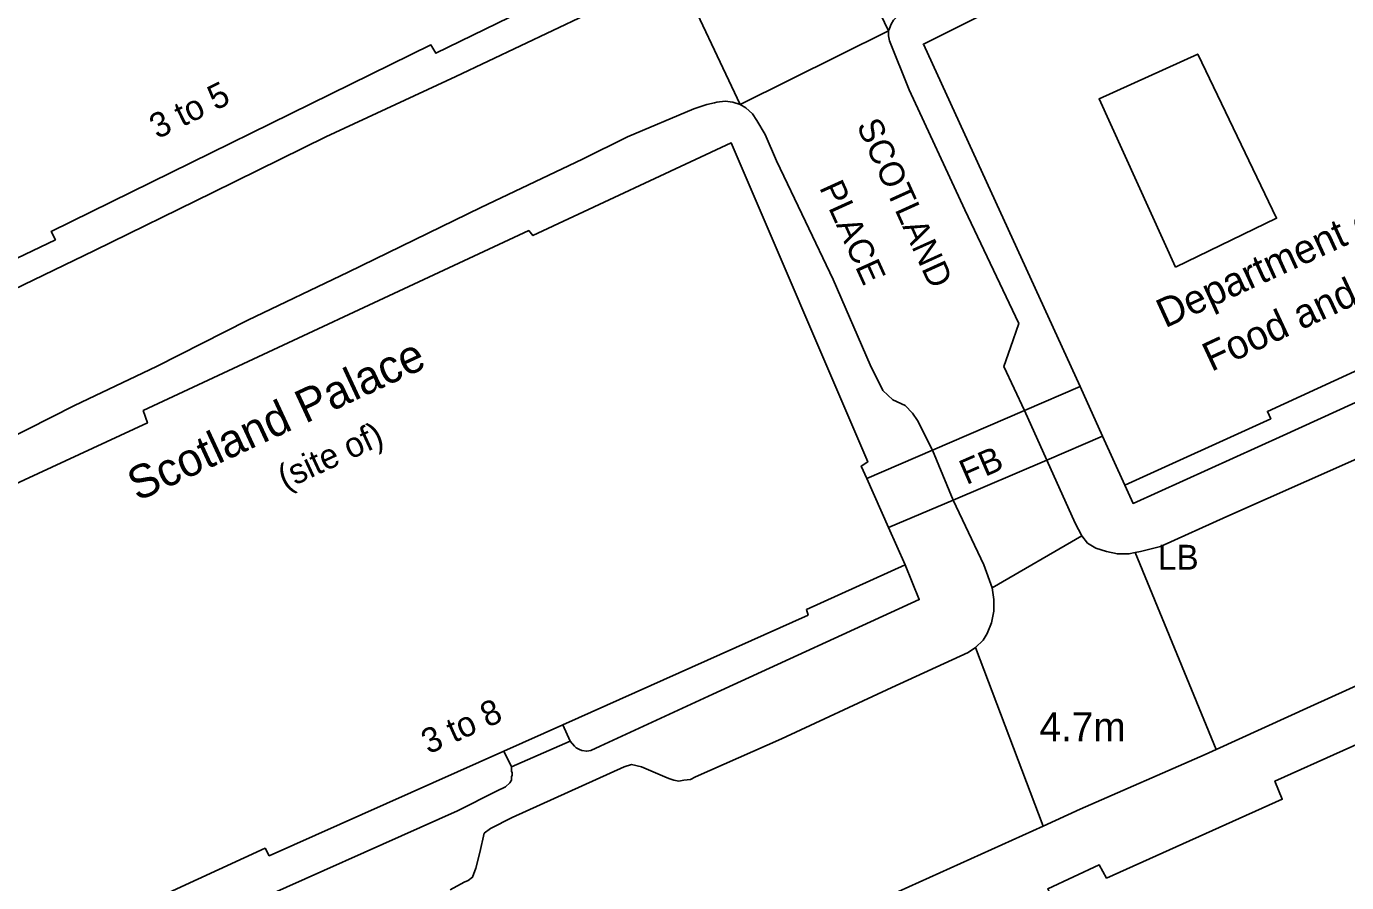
# Model space of a CAD drawing. Extents: x 529240 to 530363, y 179600 to 180767.
# Drawn here: x 530125.5 to 530205.1, y 180212.1 to 180263.8 of the extents above; entities that cross this region are included whole.
import ezdxf

# ---------------------------------------------------------------- set-up
doc = ezdxf.new("R2010")
doc.units = 0
for name, color, linetype in [('Building', 7, 'Continuous'), ('General surface', 7, 'Continuous'), ('Road Or Track', 7, 'Continuous'), ('Roadside', 7, 'Continuous'), ('Structure', 7, 'Continuous'), ('Unclassified', 7, 'Continuous')]:
    doc.layers.add(name, color=color, linetype=linetype)

msp = doc.modelspace()

# ---------------------------------------------------------------- linework, layer by layer
at = {"layer": 'Building'}
for points in [[(530120.25, 180247.55), (530127.25, 180250.9), (530127, 180251.4), (530149.9, 180262.65), (530150.2, 180262.15), (530156.85, 180265.4), (530156.7, 180265.6), (530153.1, 180272.85), (530151.05, 180271.9), (530149.15, 180275.8), (530145.1, 180284.25), (530141.55, 180291.4), (530143.35, 180292.35), (530140.7, 180297.2), (530139.75, 180299.05), (530137.25, 180297.85), (530138.3, 180295.75), (530133.7, 180293.55), (530133.15, 180294.6), (530128.85, 180292.5), (530129.4, 180291.2), (530123.5, 180288.35)], [(530206.8, 180276.35), (530200.35, 180273.1), (530179.6, 180262.7), (530189.05, 180242.05), (530190.4, 180239.05), (530191.75, 180236.1), (530200.55, 180240.1), (530200.35, 180240.55), (530210.15, 180245.05)], [(530206.8, 180276.35), (530200.35, 180273.1), (530179.6, 180262.7), (530189.05, 180242.05)], [(530116.9, 180254.6), (530120.25, 180247.55), (530127.25, 180250.9), (530127, 180251.4), (530149.9, 180262.65), (530150.2, 180262.15), (530156.85, 180265.4), (530156.7, 180265.6)], [(530194.8, 180249.25), (530190.2, 180259.4), (530196.15, 180262.1), (530200.9, 180252.2), (530194.8, 180249.25)], [(530133.05, 180211.05), (530139.9, 180214.2), (530140.15, 180213.75), (530154.3, 180220.05), (530157.85, 180221.65), (530172.65, 180228.25), (530172.55, 180228.6), (530178.5, 180231.3), (530177.5, 180233.55), (530176.2, 180236.5), (530175.85, 180237.25), (530176.25, 180237.5), (530168, 180256.75), (530156.05, 180251.15), (530155.8, 180251.45), (530132.55, 180240.6), (530132.8, 180239.85), (530104.2, 180226.6), (530106.65, 180221.35), (530106.2, 180221.15), (530107.95, 180217.25), (530107.2, 180216.85), (530109.7, 180211.2)], [(530176.2, 180236.5), (530175.85, 180237.25), (530176.25, 180237.5), (530168, 180256.75), (530156.05, 180251.15), (530155.8, 180251.45), (530132.55, 180240.6), (530132.8, 180239.85), (530104.2, 180226.6), (530106.65, 180221.35), (530106.2, 180221.15), (530107.95, 180217.25), (530107.2, 180216.85), (530109.7, 180211.2), (530110.5, 180211.55), (530112.3, 180207.4), (530112.9, 180207.55), (530115.2, 180202.3), (530115.9, 180202.6)], [(530191.75, 180236.1), (530200.55, 180240.1), (530200.35, 180240.55), (530210.15, 180245.05), (530210.4, 180244.65)], [(530189.05, 180242.05), (530190.4, 180239.05)], [(530190.4, 180239.05), (530191.75, 180236.1)], [(530177.5, 180233.55), (530176.2, 180236.5)], [(530178.5, 180231.3), (530177.5, 180233.55)], [(530157.85, 180221.65), (530172.65, 180228.25), (530172.55, 180228.6), (530178.5, 180231.3)], [(530216, 180209.297), (530216, 180222.764), (530209.9, 180220.05), (530209.05, 180221.95), (530200.8, 180218.25), (530201.25, 180217.15), (530190.65, 180212.4), (530190.2, 180213.2), (530187.1, 180211.75)], [(530168.45, 180203.4), (530176.9, 180207.35), (530177.45, 180206.4), (530187.5, 180210.95), (530187.1, 180211.75), (530190.2, 180213.2), (530190.65, 180212.4), (530201.25, 180217.15), (530200.8, 180218.25), (530209.05, 180221.95)], [(530154.3, 180220.05), (530157.85, 180221.65)], [(530133.3, 180210.6), (530133.05, 180211.05), (530139.9, 180214.2), (530140.15, 180213.75), (530154.3, 180220.05)]]:
    msp.add_lwpolyline(points, dxfattribs=at)
msp.add_lwpolyline([(530194.8, 180249.25), (530200.9, 180252.2), (530196.15, 180262.1), (530190.2, 180259.4)], close=True, dxfattribs=at)
at = {"layer": 'General surface'}
for points in [[(530194.8, 180249.25), (530200.9, 180252.2), (530196.15, 180262.1), (530190.2, 180259.4)], [(530210.4, 180244.65), (530210.15, 180245.05), (530200.35, 180240.55), (530200.55, 180240.1), (530191.75, 180236.1), (530192.25, 180235), (530201.3, 180239.1), (530210.95, 180243.5)], [(530178.5, 180231.3), (530172.55, 180228.6), (530172.65, 180228.25), (530157.85, 180221.65), (530158.3, 180220.65), (530158.55, 180220.35), (530158.65, 180220.25), (530158.85, 180220.15), (530159, 180220.1), (530159.3, 180220.05), (530159.55, 180220.1), (530160.1, 180220.35), (530166.9, 180223.5), (530179.35, 180229.2)], [(530154.75, 180219.1), (530158.3, 180220.65), (530157.85, 180221.65), (530154.3, 180220.05)], [(530134.1, 180208.65), (530137.8, 180210.35), (530151.5, 180216.45), (530153.85, 180217.65), (530154.4, 180217.9), (530154.65, 180218.15), (530154.75, 180218.3), (530154.75, 180218.5), (530154.8, 180218.6), (530154.8, 180218.75), (530154.75, 180218.85), (530154.75, 180219.1), (530154.3, 180220.05), (530140.15, 180213.75), (530139.9, 180214.2), (530133.05, 180211.05), (530133.3, 180210.6)]]:
    msp.add_lwpolyline(points, close=True, dxfattribs=at)
at = {"layer": 'Road Or Track'}
for points in [[(530177.5, 180263.5), (530177.55, 180263.65), (530177.65, 180263.9), (530177.8, 180264.15), (530178, 180264.35), (530178.4, 180264.6), (530186.7, 180268.35), (530198.2, 180273.7), (530199.55, 180274.3), (530201.65, 180275.75), (530203.95, 180277.5), (530206.15, 180279.35), (530207.7, 180280.85), (530209.65, 180283), (530211.45, 180285.2), (530212.7, 180286.9), (530214.2, 180289.3), (530215.6, 180291.8), (530216, 180292.657)], [(530173.72, 180271.41), (530177.5, 180263.5), (530177.55, 180263.65), (530177.65, 180263.9)], [(530120.4, 180245.8), (530129.6, 180250.25), (530136.75, 180253.75), (530143.55, 180257.1), (530151.4, 180260.75), (530159.2, 180264.45), (530164.76, 180267.11)], [(530177.5, 180263.5), (530177.5, 180263.2), (530177.55, 180262.9), (530178.75, 180259.95), (530182.1, 180252.7), (530185.35, 180245.85), (530184.85, 180244.4), (530184.45, 180243.25), (530185.7, 180240.6)], [(530168.55, 180259.05), (530168.1, 180259.2), (530167.65, 180259.25), (530167.15, 180259.2), (530167, 180259.15), (530166.55, 180259.05), (530165.75, 180258.8), (530161.75, 180257.1), (530159.05, 180255.75), (530152.9, 180252.85), (530144.9, 180248.95), (530138.85, 180246.05), (530133.35, 180243.25), (530128.4, 180240.9), (530124.15, 180238.75)], [(530180.15, 180238.2), (530179.25, 180240), (530178.95, 180240.45), (530178.5, 180240.9), (530177.75, 180241.25), (530177.15, 180241.8), (530176.4, 180243.35), (530174.15, 180248.5), (530172.5, 180252), (530170.75, 180255.65), (530170.05, 180257.25), (530169.55, 180258.1), (530169.3, 180258.5), (530168.9, 180258.85), (530168.55, 180259.05)], [(530192.37, 180232.03), (530192.7, 180232.1), (530193.9, 180232.4), (530197.9, 180234.2), (530205.2, 180237.45), (530213.6, 180241.2), (530216, 180242.28)], [(530187.05, 180237.6), (530185.7, 180240.6)], [(530181.4, 180235.2), (530180.15, 180238.2)], [(530187.05, 180237.6), (530188.75, 180233.8), (530189.15, 180233.05)], [(530183.75, 180229.9), (530183.25, 180231.3), (530181.4, 180235.2)], [(530189.15, 180233.05), (530189.5, 180232.6), (530190, 180232.3), (530190.65, 180232.1), (530191.3, 180231.95), (530192, 180231.95), (530192.37, 180232.03)], [(530182.75, 180226.3), (530183.2, 180226.75), (530183.45, 180227.15), (530183.7, 180227.8), (530183.85, 180228.5), (530183.85, 180229.2), (530183.75, 180229.9)], [(530197.27, 180220.16), (530202.95, 180222.75), (530216, 180228.65)], [(530172.5, 180209.05), (530186.82, 180215.54), (530182.75, 180226.3), (530182.3, 180226), (530177.7, 180223.9), (530171.05, 180220.8), (530165.85, 180218.5), (530165.55, 180218.35), (530165.15, 180218.3), (530164.85, 180218.25), (530164.55, 180218.3), (530164.25, 180218.4), (530164, 180218.5), (530162.6, 180219.1), (530162, 180219.25), (530161.55, 180219.1), (530154.8, 180216.05), (530153.5, 180215.4), (530153.1, 180215.1), (530152.85, 180213.95), (530152.6, 180213), (530152.4, 180212.45), (530152.15, 180212.25), (530151.9, 180212.15), (530151.05, 180211.7)], [(530151.05, 180211.7), (530151.9, 180212.15), (530152.15, 180212.25), (530152.4, 180212.45), (530152.6, 180213), (530152.85, 180213.95), (530153.1, 180215.1), (530153.5, 180215.4), (530154.8, 180216.05), (530161.55, 180219.1), (530162, 180219.25), (530162.6, 180219.1), (530164, 180218.5), (530164.25, 180218.4), (530164.55, 180218.3), (530164.85, 180218.25), (530165.15, 180218.3), (530165.55, 180218.35), (530165.85, 180218.5), (530171.05, 180220.8), (530177.7, 180223.9), (530182.3, 180226), (530182.75, 180226.3)], [(530186.82, 180215.54), (530189.05, 180216.55), (530196.6, 180219.85), (530197.27, 180220.16)], [(530116.65, 180183.1), (530116.95, 180183.6), (530117.35, 180184.05), (530117.75, 180184.4), (530118.5, 180184.7), (530123.65, 180187), (530130.4, 180190.15), (530137.85, 180193.45), (530144.9, 180196.55), (530152.4, 180199.95), (530158.75, 180202.8), (530165.95, 180206.05), (530172.5, 180209.05), (530186.82, 180215.54)]]:
    msp.add_lwpolyline(points, dxfattribs=at)
for points in [[(530173.72, 180271.41), (530167.05, 180268.2), (530164.76, 180267.11), (530168.55, 180259.05), (530177.5, 180263.5)], [(530164.76, 180267.11), (530159.2, 180264.45), (530151.4, 180260.75), (530143.55, 180257.1), (530136.75, 180253.75), (530129.6, 180250.25), (530120.4, 180245.8), (530124.15, 180238.75), (530128.4, 180240.9), (530133.35, 180243.25), (530138.85, 180246.05), (530144.9, 180248.95), (530152.9, 180252.85), (530159.05, 180255.75), (530161.75, 180257.1), (530165.75, 180258.8), (530166.55, 180259.05), (530167, 180259.15), (530167.15, 180259.2), (530167.65, 180259.25), (530168.1, 180259.2), (530168.55, 180259.05)], [(530180.15, 180238.2), (530185.7, 180240.6), (530184.45, 180243.25), (530184.85, 180244.4), (530185.35, 180245.85), (530182.1, 180252.7), (530178.75, 180259.95), (530177.55, 180262.9), (530177.5, 180263.2), (530177.5, 180263.5), (530168.55, 180259.05), (530168.9, 180258.85), (530169.3, 180258.5), (530169.55, 180258.1), (530170.05, 180257.25), (530170.75, 180255.65), (530172.5, 180252), (530174.15, 180248.5), (530176.4, 180243.35), (530177.15, 180241.8), (530177.75, 180241.25), (530178.5, 180240.9), (530178.95, 180240.45), (530179.25, 180240)], [(530216, 180242.28), (530213.6, 180241.2), (530205.2, 180237.45), (530197.9, 180234.2), (530193.9, 180232.4), (530192.7, 180232.1), (530192.37, 180232.03), (530197.27, 180220.16), (530202.95, 180222.75), (530216, 180228.65)], [(530181.4, 180235.2), (530183.25, 180231.3), (530183.75, 180229.9), (530189.15, 180233.05), (530188.75, 180233.8), (530187.05, 180237.6)], [(530197.27, 180220.16), (530192.37, 180232.03), (530192, 180231.95), (530191.3, 180231.95), (530190.65, 180232.1), (530190, 180232.3), (530189.5, 180232.6), (530189.15, 180233.05), (530183.75, 180229.9), (530183.85, 180229.2), (530183.85, 180228.5), (530183.7, 180227.8), (530183.45, 180227.15), (530183.2, 180226.75), (530182.75, 180226.3), (530186.82, 180215.54), (530189.05, 180216.55), (530196.6, 180219.85)]]:
    msp.add_lwpolyline(points, close=True, dxfattribs=at)
at = {"layer": 'Roadside'}
for points in [[(530206.15, 180279.35), (530203.95, 180277.5), (530201.65, 180275.75), (530199.55, 180274.3), (530198.2, 180273.7), (530186.7, 180268.35), (530178.4, 180264.6), (530178, 180264.35), (530177.8, 180264.15), (530177.65, 180263.9), (530177.55, 180263.65), (530177.5, 180263.5), (530177.5, 180263.2), (530177.55, 180262.9), (530178.75, 180259.95), (530182.1, 180252.7), (530185.35, 180245.85), (530184.85, 180244.4), (530184.45, 180243.25), (530185.7, 180240.6), (530189.05, 180242.05), (530179.6, 180262.7), (530200.35, 180273.1), (530206.8, 180276.35)], [(530156.85, 180265.4), (530150.2, 180262.15), (530149.9, 180262.65), (530127, 180251.4), (530127.25, 180250.9), (530120.25, 180247.55)], [(530120.4, 180245.8), (530129.6, 180250.25), (530136.75, 180253.75), (530143.55, 180257.1), (530151.4, 180260.75), (530159.2, 180264.45)], [(530104.2, 180226.6), (530132.8, 180239.85), (530132.55, 180240.6), (530155.8, 180251.45), (530156.05, 180251.15), (530168, 180256.75), (530176.25, 180237.5), (530175.85, 180237.25), (530176.2, 180236.5), (530180.15, 180238.2), (530179.25, 180240), (530178.95, 180240.45), (530178.5, 180240.9), (530177.75, 180241.25), (530177.15, 180241.8), (530176.4, 180243.35), (530174.15, 180248.5), (530172.5, 180252), (530170.75, 180255.65), (530170.05, 180257.25), (530169.55, 180258.1), (530169.3, 180258.5), (530168.9, 180258.85), (530168.55, 180259.05), (530168.1, 180259.2), (530167.65, 180259.25), (530167.15, 180259.2), (530167, 180259.15), (530166.55, 180259.05), (530165.75, 180258.8), (530161.75, 180257.1), (530159.05, 180255.75), (530152.9, 180252.85), (530144.9, 180248.95), (530138.85, 180246.05), (530133.35, 180243.25), (530128.4, 180240.9), (530124.15, 180238.75)], [(530151.05, 180211.7), (530151.9, 180212.15), (530152.15, 180212.25), (530152.4, 180212.45), (530152.6, 180213), (530152.85, 180213.95), (530153.1, 180215.1), (530153.5, 180215.4), (530154.8, 180216.05), (530161.55, 180219.1), (530162, 180219.25), (530162.6, 180219.1), (530164, 180218.5), (530164.25, 180218.4), (530164.55, 180218.3), (530164.85, 180218.25), (530165.15, 180218.3), (530165.55, 180218.35), (530165.85, 180218.5), (530171.05, 180220.8), (530177.7, 180223.9), (530182.3, 180226), (530182.75, 180226.3), (530183.2, 180226.75), (530183.45, 180227.15), (530183.7, 180227.8), (530183.85, 180228.5), (530183.85, 180229.2), (530183.75, 180229.9), (530183.25, 180231.3), (530181.4, 180235.2), (530177.5, 180233.55), (530178.5, 180231.3), (530179.35, 180229.2), (530166.9, 180223.5), (530160.1, 180220.35), (530159.55, 180220.1), (530159.3, 180220.05), (530159, 180220.1), (530158.85, 180220.15), (530158.65, 180220.25), (530158.55, 180220.35), (530158.3, 180220.65), (530154.75, 180219.1), (530154.75, 180218.85), (530154.8, 180218.75), (530154.8, 180218.6), (530154.75, 180218.5), (530154.75, 180218.3), (530154.65, 180218.15), (530154.4, 180217.9), (530153.85, 180217.65), (530151.5, 180216.45), (530137.8, 180210.35)], [(530187.1, 180211.75), (530190.2, 180213.2), (530190.65, 180212.4), (530201.25, 180217.15), (530200.8, 180218.25), (530209.05, 180221.95), (530216, 180224.951), (530216, 180228.65), (530202.95, 180222.75), (530197.27, 180220.16), (530196.6, 180219.85), (530189.05, 180216.55), (530186.82, 180215.54), (530172.5, 180209.05)]]:
    msp.add_lwpolyline(points, dxfattribs=at)
msp.add_lwpolyline([(530216, 180242.28), (530216, 180245.834), (530215, 180245.4), (530214.5, 180246.5), (530210.4, 180244.65), (530210.95, 180243.5), (530201.3, 180239.1), (530192.25, 180235), (530191.75, 180236.1), (530190.4, 180239.05), (530187.05, 180237.6), (530188.75, 180233.8), (530189.15, 180233.05), (530189.5, 180232.6), (530190, 180232.3), (530190.65, 180232.1), (530191.3, 180231.95), (530192, 180231.95), (530192.37, 180232.03), (530192.7, 180232.1), (530193.9, 180232.4), (530197.9, 180234.2), (530205.2, 180237.45), (530213.6, 180241.2)], close=True, dxfattribs=at)
at = {"layer": 'Structure'}
msp.add_lwpolyline([(530187.05, 180237.6), (530190.4, 180239.05), (530189.05, 180242.05), (530185.7, 180240.6), (530180.15, 180238.2), (530176.2, 180236.5), (530177.5, 180233.55), (530181.4, 180235.2)], close=True, dxfattribs=at)
at = {"layer": 'Unclassified'}
for p, q in [((530179.55, 180262.7), (530179.55, 180262.7)), ((530179.55, 180262.7), (530179.55, 180262.7)), ((530187.65, 180222.5), (530187.65, 180222.5))]:
    msp.add_line(p, q, dxfattribs=at)
for points in [[(530177.5, 180263.5), (530173.72, 180271.41)], [(530168.55, 180259.05), (530164.76, 180267.11)], [(530168.55, 180259.05), (530177.5, 180263.5)], [(530191.75, 180236.1), (530192.25, 180235), (530201.3, 180239.1), (530210.95, 180243.5)], [(530185.7, 180240.6), (530189.05, 180242.05)], [(530180.15, 180238.2), (530185.7, 180240.6)], [(530190.4, 180239.05), (530187.05, 180237.6)], [(530176.2, 180236.5), (530180.15, 180238.2)], [(530187.05, 180237.6), (530181.4, 180235.2)], [(530181.4, 180235.2), (530177.5, 180233.55)], [(530183.75, 180229.9), (530189.15, 180233.05)], [(530192.37, 180232.03), (530197.27, 180220.16)], [(530178.5, 180231.3), (530179.35, 180229.2), (530166.9, 180223.5), (530160.1, 180220.35), (530159.55, 180220.1), (530159.3, 180220.05), (530159, 180220.1), (530158.85, 180220.15), (530158.65, 180220.25), (530158.55, 180220.35), (530158.3, 180220.65)], [(530182.75, 180226.3), (530186.82, 180215.54)], [(530158.3, 180220.65), (530157.85, 180221.65)], [(530158.3, 180220.65), (530154.75, 180219.1)], [(530154.75, 180219.1), (530154.3, 180220.05)], [(530134.1, 180208.65), (530137.8, 180210.35), (530151.5, 180216.45), (530153.85, 180217.65), (530154.4, 180217.9), (530154.65, 180218.15), (530154.75, 180218.3), (530154.75, 180218.5), (530154.8, 180218.6), (530154.8, 180218.75), (530154.75, 180218.85), (530154.75, 180219.1)]]:
    msp.add_lwpolyline(points, dxfattribs=at)

# ---------------------------------------------------------------- texts
at = {"layer": 'Road Or Track'}
for s, p in [('SCOTLAND', (530175.55, 180257.8)), ('PLACE', (530173.3, 180254.05))]:
    msp.add_text(s, height=1.5, rotation=294.4, dxfattribs=at).set_placement(p)
at = {"layer": 'Structure'}
msp.add_text('FB', height=1.5, rotation=23.6, dxfattribs=at).set_placement((530182.2, 180236.1))
msp.add_text('LB', height=1.5, dxfattribs=at).set_placement((530193.75, 180231))
at = {"layer": 'Unclassified'}
for s, height, rotation, p in [('3 to 5', 1.5, 26.2, (530133.4, 180256.95)), ('Department of En', 1.75, 24.6, (530194.18, 180245.55)), ('Food and Rural A', 1.75, 25, (530196.97, 180242.92)), ('Scotland Palace', 2, 24.9, (530132.2, 180235.1)), ('(site of)', 1.5, 24.9, (530141.1, 180235.8)), ('3 to 8', 1.5, 24.3, (530149.75, 180219.85))]:
    msp.add_text(s, height=height, rotation=rotation, dxfattribs=at).set_placement(p)
msp.add_text('4.7m', height=1.75, dxfattribs=at).set_placement((530186.6, 180220.65))

doc.saveas('drawing.dxf')
